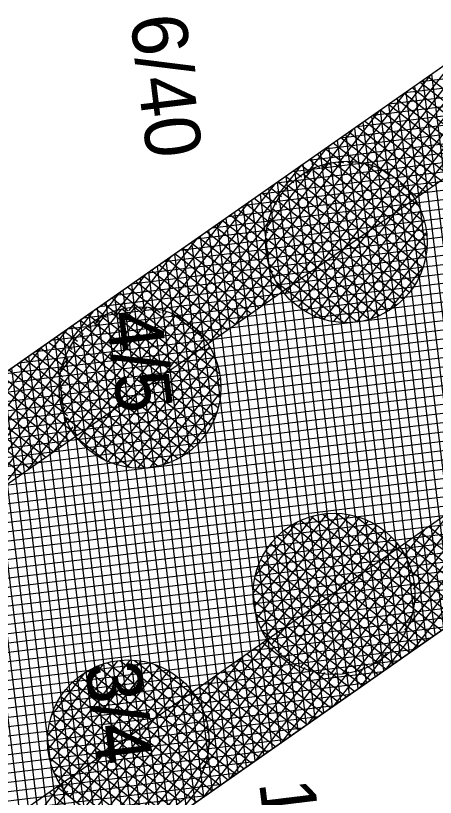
# Model space of a CAD drawing. Extents: x -566982 to -566809, y -1095912 to -1095685.
# Drawn here: x -566879.64 to -566870.56, y -1095812.81 to -1095795.86 of the extents above; entities that cross this region are included whole.
import ezdxf

# ---------------------------------------------------------------- set-up
doc = ezdxf.new("R2010")
doc.units = 0
for name, color, linetype in [('Vrstva 1', 7, 'Continuous'), ('Vrstva 40', 7, 'Continuous'), ('Vrstva 41', 7, 'Continuous'), ('Vrstva 42', 7, 'Continuous'), ('Vrstva 43', 7, 'Continuous'), ('Vrstva 44', 7, 'Continuous')]:
    doc.layers.add(name, color=color, linetype=linetype)

msp = doc.modelspace()

# ---------------------------------------------------------------- linework, layer by layer
at = {"layer": 'Vrstva 1'}
for p, q in [((-566887.09, -1095808.66), (-566860.75, -1095790.2)), ((-566853.9, -1095797.61), (-566880.71, -1095816.4))]:
    msp.add_line(p, q, dxfattribs=at)
at = {"layer": 'Vrstva 41'}
for p, q in [((-566869.525, -1095796.35), (-566871.764, -1095799.211)), ((-566870.087, -1095796.744), (-566871.958, -1095799.134)), ((-566869.794, -1095797.019), (-566871.584, -1095799.306)), ((-566870.65, -1095797.138), (-566872.17, -1095799.081)), ((-566870.716, -1095797.184), (-566869.972, -1095797.767)), ((-566870.887, -1095797.304), (-566869.952, -1095798.036)), ((-566871.058, -1095797.424), (-566869.874, -1095798.351)), ((-566871.212, -1095797.532), (-566872.404, -1095799.056)), ((-566869.956, -1095797.55), (-566871.42, -1095799.421)), ((-566871.401, -1095797.664), (-566869.754, -1095798.953)), ((-566871.23, -1095797.544), (-566869.647, -1095798.783)), ((-566871.572, -1095797.784), (-566869.925, -1095799.073)), ((-566871.774, -1095797.926), (-566872.663, -1095799.062)), ((-566871.914, -1095798.024), (-566870.268, -1095799.313)), ((-566871.743, -1095797.904), (-566870.096, -1095799.193)), ((-566869.967, -1095797.889), (-566871.27, -1095799.554)), ((-566872.086, -1095798.144), (-566870.439, -1095799.433)), ((-566869.929, -1095798.164), (-566871.134, -1095799.705)), ((-566872.336, -1095798.32), (-566872.966, -1095799.124)), ((-566872.257, -1095798.264), (-566870.61, -1095799.553)), ((-566872.599, -1095798.504), (-566871.533, -1095799.339)), ((-566872.428, -1095798.384), (-566870.781, -1095799.673)), ((-566869.856, -1095798.396), (-566870.946, -1095799.788)), ((-566872.899, -1095798.714), (-566873.347, -1095799.288)), ((-566872.77, -1095798.624), (-566872.19, -1095799.078)), ((-566873.113, -1095798.864), (-566872.826, -1095799.089)), ((-566872.942, -1095798.744), (-566872.545, -1095799.054)), ((-566873.284, -1095798.984), (-566873.065, -1095799.155)), ((-566873.461, -1095799.108), (-566876.095, -1095802.475)), ((-566873.455, -1095799.104), (-566873.272, -1095799.247)), ((-566873.798, -1095799.344), (-566873.619, -1095799.484)), ((-566873.626, -1095799.224), (-566873.456, -1095799.358)), ((-566874.023, -1095799.503), (-566876.276, -1095802.382)), ((-566873.969, -1095799.464), (-566873.762, -1095799.626)), ((-566871.319, -1095799.506), (-566870.952, -1095799.793)), ((-566874.311, -1095799.704), (-566873.993, -1095799.954)), ((-566874.14, -1095799.584), (-566873.887, -1095799.782)), ((-566874.586, -1095799.897), (-566876.474, -1095802.309)), ((-566874.482, -1095799.824), (-566874.078, -1095800.14)), ((-566874.825, -1095800.064), (-566874.186, -1095800.564)), ((-566874.654, -1095799.944), (-566874.144, -1095800.343)), ((-566874.996, -1095800.184), (-566874.2, -1095800.807)), ((-566875.148, -1095800.291), (-566876.69, -1095802.262)), ((-566874.13, -1095800.288), (-566875.929, -1095802.587)), ((-566875.167, -1095800.304), (-566874.169, -1095801.085)), ((-566875.51, -1095800.544), (-566873.863, -1095801.833)), ((-566875.338, -1095800.424), (-566874.073, -1095801.415)), ((-566875.71, -1095800.685), (-566876.928, -1095802.241)), ((-566874.197, -1095800.697), (-566875.778, -1095802.718)), ((-566875.681, -1095800.664), (-566874.034, -1095801.953)), ((-566876.023, -1095800.904), (-566874.376, -1095802.193)), ((-566875.852, -1095800.784), (-566874.205, -1095802.073)), ((-566876.273, -1095801.079), (-566877.196, -1095802.259)), ((-566876.194, -1095801.024), (-566874.548, -1095802.313)), ((-566874.183, -1095801.005), (-566875.641, -1095802.868)), ((-566876.366, -1095801.144), (-566874.719, -1095802.433)), ((-566876.708, -1095801.384), (-566875.061, -1095802.673)), ((-566876.537, -1095801.264), (-566874.89, -1095802.553)), ((-566874.127, -1095801.258), (-566875.444, -1095802.941)), ((-566876.835, -1095801.473), (-566877.509, -1095802.335)), ((-566876.879, -1095801.504), (-566875.232, -1095802.793)), ((-566874.047, -1095801.479), (-566874.882, -1095802.547)), ((-566877.222, -1095801.744), (-566876.512, -1095802.299)), ((-566877.05, -1095801.624), (-566875.404, -1095802.913)), ((-566873.944, -1095801.672), (-566874.32, -1095802.153)), ((-566877.397, -1095801.867), (-566877.94, -1095802.56)), ((-566877.393, -1095801.864), (-566876.91, -1095802.242)), ((-566877.735, -1095802.104), (-566877.46, -1095802.319)), ((-566877.564, -1095801.984), (-566877.21, -1095802.261)), ((-566877.96, -1095802.261), (-566880.926, -1095806.052)), ((-566877.907, -1095802.224), (-566877.677, -1095802.404)), ((-566878.078, -1095802.344), (-566877.866, -1095802.51)), ((-566878.42, -1095802.584), (-566878.179, -1095802.772)), ((-566878.249, -1095802.464), (-566878.032, -1095802.634)), ((-566878.522, -1095802.655), (-566881.089, -1095805.935)), ((-566878.591, -1095802.704), (-566878.308, -1095802.925)), ((-566878.934, -1095802.944), (-566878.508, -1095803.277)), ((-566878.763, -1095802.824), (-566878.418, -1095803.093)), ((-566879.084, -1095803.049), (-566881.266, -1095805.837)), ((-566879.105, -1095803.064), (-566878.576, -1095803.477)), ((-566879.276, -1095803.184), (-566878.621, -1095803.697)), ((-566878.515, -1095803.295), (-566880.778, -1095806.187)), ((-566879.619, -1095803.424), (-566878.612, -1095804.211)), ((-566879.447, -1095803.304), (-566878.638, -1095803.937)), ((-566879.79, -1095803.544), (-566878.522, -1095804.536)), ((-566878.631, -1095803.768), (-566880.644, -1095806.341)), ((-566880.132, -1095803.784), (-566878.485, -1095805.072)), ((-566879.961, -1095803.664), (-566878.314, -1095804.952)), ((-566880.303, -1095803.904), (-566878.657, -1095805.192)), ((-566878.629, -1095804.09), (-566880.505, -1095806.488)), ((-566880.475, -1095804.024), (-566878.828, -1095805.312)), ((-566880.817, -1095804.264), (-566879.17, -1095805.552)), ((-566880.646, -1095804.144), (-566878.999, -1095805.432)), ((-566880.988, -1095804.384), (-566879.341, -1095805.672)), ((-566878.582, -1095804.354), (-566879.943, -1095806.094)), ((-566881.159, -1095804.504), (-566879.513, -1095805.792)), ((-566878.504, -1095804.58), (-566879.381, -1095805.7)), ((-566878.407, -1095804.78), (-566878.818, -1095805.306)), ((-566869.655, -1095806.21), (-566871.072, -1095808.02)), ((-566869.245, -1095806.335), (-566871.048, -1095808.64)), ((-566869.374, -1095806.175), (-566871.035, -1095808.298)), ((-566869.1, -1095806.474), (-566871.222, -1095809.186)), ((-566868.941, -1095806.595), (-566871.638, -1095810.041)), ((-566870.217, -1095806.604), (-566871.144, -1095807.788)), ((-566868.767, -1095806.697), (-566871.075, -1095809.647)), ((-566870.78, -1095806.998), (-566871.238, -1095807.583)), ((-566870.698, -1095806.941), (-566869.051, -1095808.229)), ((-566871.04, -1095807.181), (-566869.394, -1095808.469)), ((-566870.869, -1095807.061), (-566869.223, -1095808.349)), ((-566871.212, -1095807.301), (-566869.565, -1095808.589)), ((-566871.342, -1095807.392), (-566871.35, -1095807.403)), ((-566871.287, -1095807.495), (-566869.736, -1095808.709)), ((-566871.109, -1095807.889), (-566869.908, -1095808.829)), ((-566871.042, -1095808.195), (-566870.079, -1095808.949)), ((-566871.033, -1095808.456), (-566870.25, -1095809.069)), ((-566871.056, -1095808.692), (-566870.421, -1095809.189)), ((-566871.106, -1095808.907), (-566870.592, -1095809.309)), ((-566871.181, -1095809.102), (-566870.764, -1095809.429)), ((-566874.163, -1095809.375), (-566875.551, -1095811.148)), ((-566871.276, -1095809.282), (-566870.935, -1095809.549)), ((-566874.036, -1095809.537), (-566875.503, -1095811.411)), ((-566874.293, -1095809.461), (-566872.647, -1095810.749)), ((-566871.389, -1095809.448), (-566871.106, -1095809.669)), ((-566873.895, -1095809.681), (-566875.499, -1095811.731)), ((-566874.636, -1095809.701), (-566872.989, -1095810.989)), ((-566874.464, -1095809.581), (-566872.818, -1095810.869)), ((-566871.619, -1095809.693), (-566872.2, -1095810.436)), ((-566871.52, -1095809.599), (-566871.277, -1095809.789)), ((-566874.717, -1095809.757), (-566875.628, -1095810.922)), ((-566873.739, -1095809.806), (-566875.609, -1095812.195)), ((-566874.807, -1095809.821), (-566873.16, -1095811.109)), ((-566871.838, -1095809.858), (-566871.62, -1095810.029)), ((-566871.67, -1095809.736), (-566871.448, -1095809.909)), ((-566873.567, -1095809.911), (-566876.136, -1095813.195)), ((-566873.381, -1095809.997), (-566875.574, -1095812.8)), ((-566875.149, -1095810.06), (-566873.503, -1095811.349)), ((-566873.178, -1095810.063), (-566875.012, -1095812.406)), ((-566874.978, -1095809.941), (-566873.332, -1095811.229)), ((-566873.209, -1095810.055), (-566872.476, -1095810.629)), ((-566872.107, -1095809.993), (-566872.762, -1095810.83)), ((-566872.25, -1095810.043), (-566871.962, -1095810.269)), ((-566872.03, -1095809.962), (-566871.791, -1095810.149)), ((-566875.279, -1095810.151), (-566875.726, -1095810.722)), ((-566875.32, -1095810.18), (-566873.674, -1095811.469)), ((-566872.957, -1095810.105), (-566874.449, -1095812.012)), ((-566872.707, -1095810.11), (-566873.887, -1095811.618)), ((-566872.436, -1095810.089), (-566873.325, -1095811.224)), ((-566872.812, -1095810.112), (-566872.304, -1095810.509)), ((-566872.502, -1095810.1), (-566872.133, -1095810.389)), ((-566875.492, -1095810.3), (-566873.845, -1095811.589)), ((-566875.841, -1095810.546), (-566875.842, -1095810.546)), ((-566875.834, -1095810.54), (-566874.188, -1095811.829)), ((-566875.663, -1095810.42), (-566874.016, -1095811.709)), ((-566875.608, -1095810.971), (-566874.359, -1095811.949)), ((-566875.519, -1095811.295), (-566874.53, -1095812.069)), ((-566875.493, -1095811.569), (-566874.701, -1095812.189)), ((-566875.51, -1095811.81), (-566874.872, -1095812.309)), ((-566875.554, -1095812.029), (-566875.044, -1095812.429)), ((-566875.621, -1095812.23), (-566875.215, -1095812.549)), ((-566875.709, -1095812.416), (-566875.386, -1095812.669)), ((-566878.653, -1095812.516), (-566880.078, -1095814.338)), ((-566878.744, -1095812.58), (-566877.098, -1095813.869)), ((-566875.818, -1095812.585), (-566875.557, -1095812.789)), ((-566878.524, -1095812.677), (-566880.035, -1095814.607)), ((-566878.915, -1095812.7), (-566877.269, -1095813.988)), ((-566875.944, -1095812.74), (-566875.728, -1095812.909))]:
    msp.add_line(p, q, dxfattribs=at)
at = {"layer": 'Vrstva 42'}
for points in [[(-566834.15, -1095760.69), (-566836.072, -1095760.136), (-566841.286, -1095779.189), (-566855.268, -1095796.126), (-566881.984, -1095814.851), (-566891.818, -1095824.318), (-566954.342, -1095716.292), (-566956.66, -1095716.28), (-566892.27, -1095827.53), (-566880.71, -1095816.4), (-566853.9, -1095797.61), (-566839.47, -1095780.13)], [(-566945.07, -1095716.34), (-566947.388, -1095716.328), (-566890.462, -1095814.681), (-566885.816, -1095810.21), (-566859.382, -1095791.684), (-566846.734, -1095776.361), (-566841.831, -1095758.448), (-566843.76, -1095757.92), (-566848.55, -1095775.42), (-566860.75, -1095790.2), (-566887.09, -1095808.66), (-566890.01, -1095811.47)]]:
    msp.add_lwpolyline(points, close=True, dxfattribs=at)
at = {"layer": 'Vrstva 43'}
for p, q in [((-566870.867, -1095797.29), (-566851.706, -1095794.952)), ((-566871.215, -1095797.534), (-566851.891, -1095795.176)), ((-566871.563, -1095797.778), (-566852.076, -1095795.4)), ((-566871.911, -1095798.022), (-566852.261, -1095795.624)), ((-566872.259, -1095798.266), (-566852.446, -1095795.848)), ((-566872.607, -1095798.51), (-566852.631, -1095796.072)), ((-566872.955, -1095798.754), (-566852.815, -1095796.296)), ((-566873.303, -1095798.998), (-566853, -1095796.52)), ((-566873.652, -1095799.242), (-566853.185, -1095796.744)), ((-566874, -1095799.486), (-566853.37, -1095796.968)), ((-566870.639, -1095797.13), (-566869.266, -1095808.38)), ((-566874.348, -1095799.73), (-566853.555, -1095797.192)), ((-566870.825, -1095797.261), (-566869.452, -1095808.51)), ((-566874.696, -1095799.974), (-566853.74, -1095797.417)), ((-566871.196, -1095797.521), (-566869.823, -1095808.77)), ((-566871.01, -1095797.391), (-566869.637, -1095808.64)), ((-566875.044, -1095800.218), (-566853.947, -1095797.643)), ((-566871.381, -1095797.651), (-566870.009, -1095808.9)), ((-566871.567, -1095797.781), (-566870.194, -1095809.03)), ((-566875.392, -1095800.462), (-566854.296, -1095797.887)), ((-566871.753, -1095797.911), (-566870.38, -1095809.16)), ((-566875.74, -1095800.706), (-566854.644, -1095798.131)), ((-566872.124, -1095798.171), (-566870.751, -1095809.42)), ((-566871.938, -1095798.041), (-566870.565, -1095809.29)), ((-566876.088, -1095800.95), (-566854.992, -1095798.375)), ((-566872.309, -1095798.301), (-566870.937, -1095809.55)), ((-566872.495, -1095798.431), (-566871.122, -1095809.68)), ((-566876.436, -1095801.194), (-566855.34, -1095798.619)), ((-566872.866, -1095798.691), (-566871.493, -1095809.941)), ((-566872.681, -1095798.561), (-566871.308, -1095809.81)), ((-566876.784, -1095801.438), (-566855.688, -1095798.863)), ((-566873.052, -1095798.822), (-566871.679, -1095810.071)), ((-566873.237, -1095798.952), (-566871.865, -1095810.201)), ((-566877.133, -1095801.681), (-566856.036, -1095799.107)), ((-566873.609, -1095799.212), (-566872.236, -1095810.461)), ((-566873.423, -1095799.082), (-566872.05, -1095810.331)), ((-566877.481, -1095801.925), (-566856.384, -1095799.351)), ((-566873.794, -1095799.342), (-566872.422, -1095810.591)), ((-566873.98, -1095799.472), (-566872.607, -1095810.721)), ((-566877.829, -1095802.169), (-566856.732, -1095799.595)), ((-566874.351, -1095799.732), (-566872.978, -1095810.981)), ((-566874.165, -1095799.602), (-566872.793, -1095810.851)), ((-566878.177, -1095802.413), (-566857.08, -1095799.839)), ((-566874.537, -1095799.862), (-566873.164, -1095811.111)), ((-566874.722, -1095799.992), (-566873.35, -1095811.241)), ((-566878.525, -1095802.657), (-566857.428, -1095800.083)), ((-566874.908, -1095800.122), (-566873.535, -1095811.371)), ((-566878.873, -1095802.901), (-566857.776, -1095800.327)), ((-566875.279, -1095800.383), (-566873.906, -1095811.632)), ((-566875.094, -1095800.252), (-566873.721, -1095811.502)), ((-566879.221, -1095803.145), (-566858.125, -1095800.571)), ((-566875.465, -1095800.513), (-566874.092, -1095811.762)), ((-566875.65, -1095800.643), (-566874.278, -1095811.892)), ((-566879.569, -1095803.389), (-566858.473, -1095800.815)), ((-566876.022, -1095800.903), (-566874.649, -1095812.152)), ((-566875.836, -1095800.773), (-566874.463, -1095812.022)), ((-566879.917, -1095803.633), (-566858.821, -1095801.059)), ((-566876.207, -1095801.033), (-566874.834, -1095812.282)), ((-566876.393, -1095801.163), (-566875.02, -1095812.412)), ((-566880.265, -1095803.877), (-566859.169, -1095801.303)), ((-566876.764, -1095801.423), (-566875.391, -1095812.672)), ((-566876.578, -1095801.293), (-566875.206, -1095812.542)), ((-566880.614, -1095804.121), (-566859.517, -1095801.547)), ((-566876.95, -1095801.553), (-566875.577, -1095812.802)), ((-566877.135, -1095801.683), (-566875.762, -1095812.933)), ((-566880.962, -1095804.365), (-566859.865, -1095801.791)), ((-566877.321, -1095801.813), (-566875.948, -1095813.063)), ((-566881.31, -1095804.609), (-566860.213, -1095802.035)), ((-566877.692, -1095802.074), (-566876.319, -1095813.323)), ((-566877.506, -1095801.944), (-566876.134, -1095813.193)), ((-566877.878, -1095802.204), (-566876.505, -1095813.453)), ((-566881.658, -1095804.853), (-566860.561, -1095802.279)), ((-566878.063, -1095802.334), (-566876.691, -1095813.583)), ((-566882.006, -1095805.097), (-566860.909, -1095802.523)), ((-566878.435, -1095802.594), (-566877.062, -1095813.843)), ((-566878.249, -1095802.464), (-566876.876, -1095813.713)), ((-566882.354, -1095805.341), (-566861.257, -1095802.766)), ((-566878.62, -1095802.724), (-566877.247, -1095813.973)), ((-566878.806, -1095802.854), (-566877.433, -1095814.103)), ((-566882.702, -1095805.585), (-566861.605, -1095803.01)), ((-566879.177, -1095803.114), (-566877.804, -1095814.363)), ((-566878.991, -1095802.984), (-566877.619, -1095814.233)), ((-566883.05, -1095805.829), (-566861.954, -1095803.254)), ((-566879.363, -1095803.244), (-566877.99, -1095814.494)), ((-566879.548, -1095803.374), (-566878.175, -1095814.624)), ((-566883.398, -1095806.073), (-566862.302, -1095803.498)), ((-566879.734, -1095803.505), (-566878.361, -1095814.754)), ((-566883.747, -1095806.317), (-566862.65, -1095803.742)), ((-566880.105, -1095803.765), (-566878.732, -1095815.014)), ((-566879.919, -1095803.635), (-566878.547, -1095814.884)), ((-566880.291, -1095803.895), (-566878.918, -1095815.144)), ((-566884.095, -1095806.561), (-566862.998, -1095803.986)), ((-566880.476, -1095804.025), (-566879.103, -1095815.274)), ((-566884.443, -1095806.805), (-566863.346, -1095804.23)), ((-566880.662, -1095804.155), (-566879.289, -1095815.404)), ((-566884.791, -1095807.049), (-566863.694, -1095804.474)), ((-566885.139, -1095807.293), (-566864.042, -1095804.718)), ((-566885.487, -1095807.537), (-566864.39, -1095804.962)), ((-566885.835, -1095807.781), (-566864.738, -1095805.206)), ((-566886.183, -1095808.025), (-566865.086, -1095805.45)), ((-566886.531, -1095808.268), (-566865.434, -1095805.694)), ((-566886.879, -1095808.512), (-566865.783, -1095805.938)), ((-566887.185, -1095808.751), (-566866.131, -1095806.182)), ((-566887.425, -1095808.982), (-566866.479, -1095806.426)), ((-566887.664, -1095809.213), (-566866.827, -1095806.67)), ((-566887.904, -1095809.443), (-566867.175, -1095806.914)), ((-566888.144, -1095809.674), (-566867.523, -1095807.158)), ((-566888.384, -1095809.905), (-566867.871, -1095807.402)), ((-566888.623, -1095810.136), (-566868.219, -1095807.646)), ((-566888.863, -1095810.366), (-566868.567, -1095807.89)), ((-566889.103, -1095810.597), (-566868.915, -1095808.134)), ((-566889.343, -1095810.828), (-566869.263, -1095808.378)), ((-566889.583, -1095811.059), (-566869.612, -1095808.622)), ((-566889.822, -1095811.289), (-566869.96, -1095808.866)), ((-566900.779, -1095812.828), (-566870.308, -1095809.109)), ((-566900.67, -1095813.016), (-566870.656, -1095809.353)), ((-566900.562, -1095813.204), (-566871.004, -1095809.597)), ((-566900.453, -1095813.393), (-566871.352, -1095809.841)), ((-566900.344, -1095813.581), (-566871.7, -1095810.085)), ((-566900.235, -1095813.769), (-566872.048, -1095810.329)), ((-566900.126, -1095813.957), (-566872.396, -1095810.573)), ((-566900.017, -1095814.145), (-566872.744, -1095810.817)), ((-566899.908, -1095814.333), (-566873.092, -1095811.061)), ((-566899.799, -1095814.522), (-566873.44, -1095811.305)), ((-566899.69, -1095814.71), (-566873.789, -1095811.549)), ((-566899.581, -1095814.898), (-566874.137, -1095811.793)), ((-566899.472, -1095815.086), (-566874.485, -1095812.037)), ((-566899.363, -1095815.274), (-566874.833, -1095812.281)), ((-566899.254, -1095815.463), (-566875.181, -1095812.525)), ((-566899.146, -1095815.651), (-566875.529, -1095812.769))]:
    msp.add_line(p, q, dxfattribs=at)
msp.add_lwpolyline([(-566834.15, -1095760.69), (-566843.76, -1095757.92), (-566848.55, -1095775.42), (-566860.75, -1095790.2), (-566887.09, -1095808.66), (-566890.01, -1095811.47), (-566945.07, -1095716.34), (-566956.66, -1095716.28), (-566892.27, -1095827.53), (-566880.71, -1095816.4), (-566853.9, -1095797.61), (-566839.47, -1095780.13)], close=True, dxfattribs=at)
at = {"layer": 'Vrstva 44'}
for p, q in [((-566872.587, -1095799.026), (-566874.2, -1095801.088)), ((-566872.335, -1095799.029), (-566874.139, -1095801.334)), ((-566872.762, -1095799.045), (-566870.739, -1095800.628)), ((-566872.467, -1095799.022), (-566870.789, -1095800.335)), ((-566872.873, -1095799.068), (-566874.23, -1095800.801)), ((-566873.22, -1095799.187), (-566874.197, -1095800.435)), ((-566872.107, -1095799.063), (-566874.049, -1095801.544)), ((-566871.9, -1095799.123), (-566873.942, -1095801.732)), ((-566871.709, -1095799.203), (-566873.819, -1095801.899)), ((-566873.227, -1095799.19), (-566870.767, -1095801.114)), ((-566873.01, -1095799.105), (-566870.735, -1095800.885)), ((-566872.082, -1095799.069), (-566870.926, -1095799.974)), ((-566871.533, -1095799.302), (-566873.68, -1095802.046)), ((-566873.418, -1095799.294), (-566870.823, -1095801.324)), ((-566873.735, -1095799.553), (-566870.997, -1095801.696)), ((-566873.586, -1095799.416), (-566870.9, -1095801.518)), ((-566871.371, -1095799.419), (-566873.526, -1095802.174)), ((-566871.224, -1095799.556), (-566873.358, -1095802.284)), ((-566873.867, -1095799.705), (-566871.113, -1095801.859)), ((-566871.091, -1095799.712), (-566873.176, -1095802.376)), ((-566873.98, -1095799.869), (-566871.247, -1095802.009)), ((-566870.974, -1095799.886), (-566872.979, -1095802.449)), ((-566874.075, -1095800.05), (-566871.398, -1095802.144)), ((-566870.873, -1095800.082), (-566872.763, -1095802.497)), ((-566874.149, -1095800.246), (-566871.569, -1095802.264)), ((-566870.796, -1095800.308), (-566872.528, -1095802.521)), ((-566874.201, -1095800.458), (-566871.764, -1095802.366)), ((-566870.744, -1095800.566), (-566872.262, -1095802.506)), ((-566874.229, -1095800.691), (-566871.984, -1095802.447)), ((-566870.735, -1095800.879), (-566871.955, -1095802.438)), ((-566874.22, -1095800.951), (-566872.238, -1095802.503)), ((-566874.162, -1095801.251), (-566872.54, -1095802.52)), ((-566870.818, -1095801.31), (-566871.561, -1095802.259)), ((-566874.008, -1095801.625), (-566872.944, -1095802.458)), ((-566877.351, -1095802.224), (-566878.7, -1095803.949)), ((-566877.063, -1095802.181), (-566878.672, -1095804.238)), ((-566876.811, -1095802.184), (-566878.611, -1095804.484)), ((-566876.583, -1095802.216), (-566878.522, -1095804.695)), ((-566877.345, -1095802.223), (-566875.203, -1095803.898)), ((-566877.073, -1095802.181), (-566875.231, -1095803.623)), ((-566876.737, -1095802.19), (-566875.321, -1095803.299)), ((-566877.699, -1095802.345), (-566878.666, -1095803.58)), ((-566876.375, -1095802.276), (-566878.415, -1095804.883)), ((-566876.184, -1095802.356), (-566878.292, -1095805.05)), ((-566877.783, -1095802.388), (-566875.258, -1095804.363)), ((-566877.58, -1095802.293), (-566875.217, -1095804.141)), ((-566876.227, -1095802.335), (-566875.582, -1095802.84)), ((-566876.007, -1095802.455), (-566878.154, -1095805.198)), ((-566875.845, -1095802.571), (-566878, -1095805.326)), ((-566877.964, -1095802.5), (-566875.324, -1095804.565)), ((-566878.267, -1095802.771), (-566875.516, -1095804.923)), ((-566878.124, -1095802.628), (-566875.411, -1095804.751)), ((-566875.698, -1095802.708), (-566877.833, -1095805.436)), ((-566878.389, -1095802.929), (-566875.639, -1095805.081)), ((-566875.565, -1095802.863), (-566877.651, -1095805.529)), ((-566878.493, -1095803.101), (-566875.78, -1095805.225)), ((-566875.447, -1095803.037), (-566877.454, -1095805.602)), ((-566878.58, -1095803.288), (-566875.941, -1095805.353)), ((-566875.346, -1095803.232), (-566877.238, -1095805.651)), ((-566875.268, -1095803.457), (-566877.004, -1095805.675)), ((-566878.646, -1095803.49), (-566876.122, -1095805.465)), ((-566878.687, -1095803.712), (-566876.326, -1095805.559)), ((-566875.215, -1095803.714), (-566876.739, -1095805.661)), ((-566878.7, -1095803.955), (-566876.56, -1095805.63)), ((-566875.206, -1095804.027), (-566876.433, -1095805.595)), ((-566878.674, -1095804.23), (-566876.831, -1095805.672)), ((-566875.286, -1095804.453), (-566876.043, -1095805.422)), ((-566878.583, -1095804.555), (-566877.167, -1095805.663)), ((-566878.32, -1095805.015), (-566877.681, -1095805.515)), ((-566872.898, -1095806.657), (-566874.476, -1095808.674)), ((-566872.643, -1095806.655), (-566874.418, -1095808.924)), ((-566872.993, -1095806.669), (-566871.01, -1095808.221)), ((-566872.69, -1095806.652), (-566871.068, -1095807.921)), ((-566873.192, -1095806.708), (-566874.497, -1095808.376)), ((-566873.555, -1095806.848), (-566874.45, -1095807.992)), ((-566872.411, -1095806.684), (-566874.334, -1095809.141)), ((-566872.201, -1095806.74), (-566874.229, -1095809.331)), ((-566872.007, -1095806.817), (-566874.107, -1095809.501)), ((-566873.467, -1095806.806), (-566871.029, -1095808.714)), ((-566873.248, -1095806.724), (-566871.003, -1095808.48)), ((-566872.286, -1095806.714), (-566871.222, -1095807.547)), ((-566871.829, -1095806.914), (-566873.971, -1095809.652)), ((-566873.662, -1095806.908), (-566871.082, -1095808.926)), ((-566873.984, -1095807.163), (-566871.25, -1095809.302)), ((-566873.833, -1095807.027), (-566871.157, -1095809.122)), ((-566871.665, -1095807.028), (-566873.82, -1095809.783)), ((-566871.514, -1095807.161), (-566873.655, -1095809.896)), ((-566874.118, -1095807.312), (-566871.364, -1095809.467)), ((-566871.38, -1095807.313), (-566873.475, -1095809.99)), ((-566874.234, -1095807.476), (-566871.496, -1095809.618)), ((-566871.26, -1095807.485), (-566873.28, -1095810.066)), ((-566874.332, -1095807.653), (-566871.645, -1095809.755)), ((-566871.157, -1095807.677), (-566873.067, -1095810.119)), ((-566874.408, -1095807.847), (-566871.814, -1095809.877)), ((-566871.075, -1095807.897), (-566872.835, -1095810.147)), ((-566874.464, -1095808.058), (-566872.004, -1095809.982)), ((-566871.019, -1095808.15), (-566872.576, -1095810.14)), ((-566874.495, -1095808.287), (-566872.221, -1095810.066)), ((-566874.491, -1095808.544), (-566872.468, -1095810.127)), ((-566871.002, -1095808.453), (-566872.278, -1095810.084)), ((-566874.443, -1095808.836), (-566872.765, -1095810.149)), ((-566871.058, -1095808.849), (-566871.903, -1095809.93)), ((-566874.305, -1095809.198), (-566873.147, -1095810.104)), ((-566877.437, -1095809.851), (-566878.944, -1095811.776)), ((-566877.171, -1095809.834), (-566878.895, -1095812.038)), ((-566876.934, -1095809.857), (-566878.817, -1095812.263)), ((-566877.652, -1095809.892), (-566875.459, -1095811.608)), ((-566877.389, -1095809.844), (-566875.474, -1095811.342)), ((-566877.069, -1095809.841), (-566875.546, -1095811.032)), ((-566877.746, -1095809.921), (-566878.951, -1095811.461)), ((-566876.718, -1095809.904), (-566878.719, -1095812.462)), ((-566876.519, -1095809.975), (-566878.602, -1095812.637)), ((-566876.337, -1095810.067), (-566878.469, -1095812.792)), ((-566878.077, -1095810.067), (-566875.525, -1095812.064)), ((-566877.878, -1095809.969), (-566875.478, -1095811.848)), ((-566876.623, -1095809.936), (-566875.746, -1095810.622)), ((-566878.147, -1095810.108), (-566878.864, -1095811.024)), ((-566876.169, -1095810.177), (-566878.323, -1095812.929)), ((-566878.254, -1095810.183), (-566875.596, -1095812.263)), ((-566878.411, -1095810.314), (-566875.686, -1095812.446)), ((-566876.015, -1095810.304), (-566878.162, -1095813.049)), ((-566878.547, -1095810.461), (-566875.794, -1095812.615)), ((-566875.874, -1095810.45), (-566877.987, -1095813.149)), ((-566878.666, -1095810.622), (-566875.921, -1095812.77)), ((-566875.75, -1095810.615), (-566877.796, -1095813.229)), ((-566878.768, -1095810.797), (-566876.067, -1095812.91)), ((-566875.643, -1095810.802), (-566877.59, -1095813.291)), ((-566878.851, -1095810.986), (-566876.232, -1095813.035)), ((-566875.553, -1095811.013), (-566877.362, -1095813.325)), ((-566878.911, -1095811.193), (-566876.417, -1095813.144)), ((-566875.489, -1095811.255), (-566877.112, -1095813.33)), ((-566878.947, -1095811.419), (-566876.627, -1095813.233)), ((-566875.457, -1095811.539), (-566876.827, -1095813.29)), ((-566878.954, -1095811.667), (-566876.869, -1095813.299)), ((-566875.487, -1095811.902), (-566876.484, -1095813.175)), ((-566878.916, -1095811.95), (-566877.152, -1095813.331)), ((-566878.807, -1095812.29), (-566877.51, -1095813.305))]:
    msp.add_line(p, q, dxfattribs=at)
for centre in [(-566872.481, -1095800.771), (-566876.952, -1095803.926), (-566872.749, -1095808.4), (-566877.207, -1095811.583)]:
    msp.add_circle(centre, 1.75, dxfattribs=at)

# ---------------------------------------------------------------- texts
at = {"layer": 'Vrstva 40'}
for s, p in [('6/40', (-566877.166, -1095795.903)), ('4/5', (-566877.693, -1095802.314)), ('3/4', (-566878.143, -1095809.935)), ('10/40', (-566874.376, -1095812.487))]:
    msp.add_text(s, height=1.2, rotation=276.9575, dxfattribs=at).set_placement(p)

doc.saveas('drawing.dxf')
